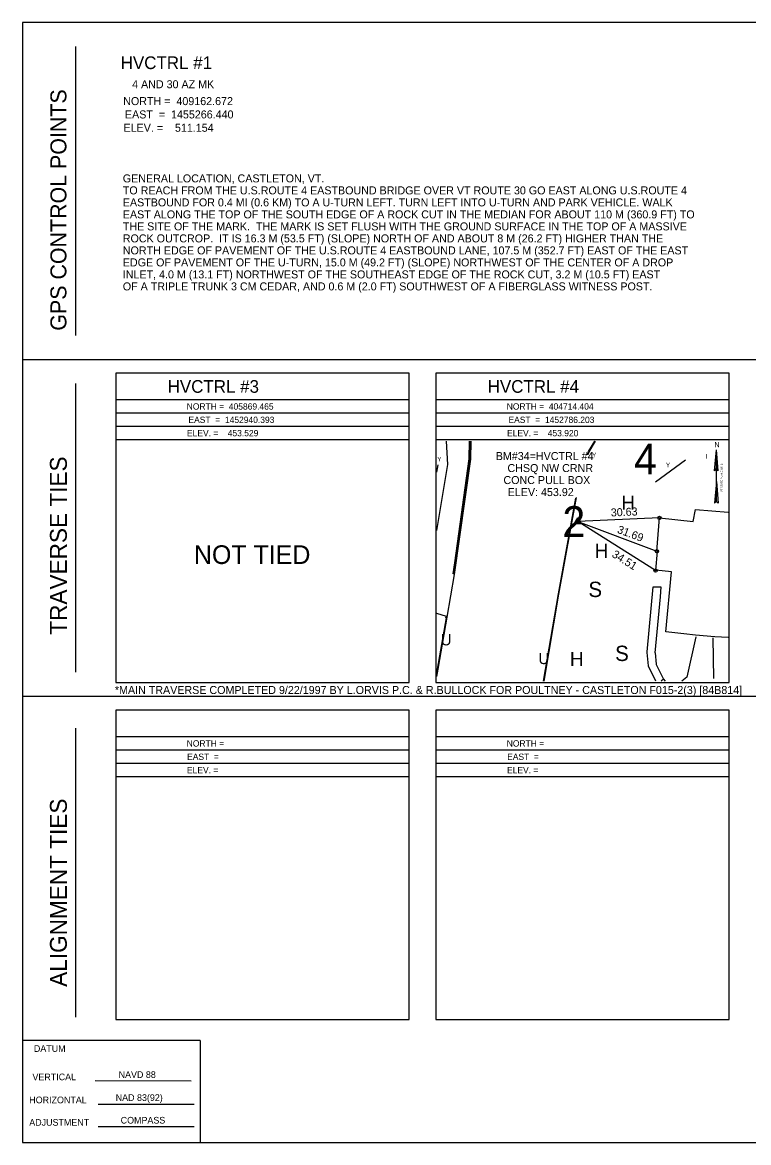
# Model space of a CAD drawing. Extents: x 1452748 to 1453388, y 402871 to 403291.
# Drawn here: x 1452747.7 to 1453020, y 402870.9 to 403290.9 of the extents above; entities that cross this region are included whole.
import ezdxf

# ---------------------------------------------------------------- set-up
doc = ezdxf.new("R2010")
doc.units = 0
for name, color, linetype in [('C_C', 7, 'Continuous'), ('CBP', 7, 'Continuous'), ('CPSM', 7, 'Continuous'), ('Default', 7, 'Continuous'), ('Level 1', 7, 'Continuous'), ('Level 11', 7, 'Continuous'), ('Level 12', 7, 'Continuous'), ('Level 13', 7, 'Continuous'), ('Level 14', 7, 'Continuous'), ('Level 15', 7, 'Continuous'), ('Level 16', 7, 'Continuous'), ('Level 43', 7, 'Continuous'), ('NBL1', 7, 'Continuous'), ('NBL2', 7, 'Continuous'), ('NNA_P', 7, 'Continuous')]:
    doc.layers.add(name, color=color, linetype=linetype)

msp = doc.modelspace()

# ---------------------------------------------------------------- linework, layer by layer
at = {"layer": 'CBP'}
for centre, radius in [((1452986.52, 403105.09), 0.625), ((1452986.52, 403105.09), 0.0833), ((1452985.59, 403092.61), 0.625), ((1452985.59, 403092.61), 0.0833), ((1452985.12, 403085.37), 0.625), ((1452985.12, 403085.37), 0.0833)]:
    msp.add_circle(centre, radius, dxfattribs=at)
at = {"layer": 'CPSM'}
for p, q in [((1452954.66, 403103.04), (1452955.91, 403105.2)), ((1452954.66, 403103.04), (1452955.92, 403103.76)), ((1452957.16, 403103.04), (1452955.91, 403105.2)), ((1452955.92, 403103.76), (1452955.91, 403105.2)), ((1452955.92, 403103.76), (1452955.92, 403103.76)), ((1452955.92, 403103.76), (1452957.16, 403103.04)), ((1452954.66, 403103.04), (1452957.16, 403103.04))]:
    msp.add_line(p, q, dxfattribs=at)
at = {"layer": 'Default'}
for p, q in [((1452986.52, 403105.09), (1452955.92, 403103.76)), ((1452955.92, 403103.76), (1452985.59, 403092.61)), ((1452985.12, 403085.37), (1452955.92, 403103.76))]:
    msp.add_line(p, q, dxfattribs=at)
at = {"layer": 'Level 11'}
for p, q in [((1452907.2, 403125.18), (1452906.75, 403133.85)), ((1452915.24, 403133.85), (1452915.08, 403127.24)), ((1452915.37, 403133.85), (1452915.23, 403127.2)), ((1452915.6, 403127.09), (1452915.8, 403133.85)), ((1452915.76, 403127.1), (1452916, 403133.85)), ((1452959.93, 403129.96), (1452962.34, 403133.85)), ((1452960.17, 403129.84), (1452962.59, 403133.85)), ((1452959.54, 403128.83), (1452959.93, 403129.96)), ((1452959.85, 403128.94), (1452960.17, 403129.84)), ((1452903.07, 403100.45), (1452907.2, 403125.18)), ((1452909.65, 403083.95), (1452915.76, 403127.1)), ((1452909.67, 403084.19), (1452915.6, 403127.09)), ((1452915.08, 403127.24), (1452909.75, 403088.26)), ((1452915.23, 403127.2), (1452909.81, 403088.14)), ((1452948.73, 403076.64), (1452955.23, 403112.5)), ((1452948.87, 403076.47), (1452955.48, 403112.75)), ((1452909.75, 403088.26), (1452909.06, 403084.16)), ((1452909.81, 403088.14), (1452909.22, 403084.21)), ((1452906.92, 403067.89), (1452909.65, 403083.95)), ((1452909.22, 403084.21), (1452909.67, 403084.19)), ((1452943.08, 403043.88), (1452948.73, 403076.64)), ((1452943.31, 403043.88), (1452948.87, 403076.47)), ((1452906.65, 403068.12), (1452903.07, 403069.31)), ((1452903.37, 403048.34), (1452906.74, 403067.64)), ((1452903.58, 403048.39), (1452906.92, 403067.89)), ((1452906.74, 403067.64), (1452906.29, 403067.78)), ((1453000.13, 403060.53), (1452996.85, 403045.45)), ((1453006.95, 403044.88), (1453006.63, 403060.13)), ((1452903.07, 403045.62), (1452903.58, 403048.39)), ((1452903.07, 403046.29), (1452903.37, 403048.34)), ((1452996.85, 403045.45), (1452994.92, 403043.88))]:
    msp.add_line(p, q, dxfattribs=at)
at = {"layer": 'Level 12'}
for p, q in [((1452903.07, 403122.29), (1452903.56, 403125.04)), ((1452981.96, 403054.9), (1452984.15, 403079.21)), ((1452984.15, 403079.21), (1452987.04, 403079.23)), ((1452987.04, 403079.23), (1452986.81, 403075.51)), ((1452986.81, 403075.51), (1452984.87, 403054.58)), ((1452981.98, 403054.71), (1452981.96, 403054.9)), ((1452982.42, 403049.68), (1452981.98, 403054.71)), ((1452984.87, 403054.58), (1452984.89, 403054.47)), ((1452984.89, 403054.47), (1452985.34, 403050.27)), ((1452982.43, 403049.52), (1452982.42, 403049.68)), ((1452985.24, 403043.88), (1452982.43, 403049.52)), ((1452985.34, 403050.27), (1452985.34, 403050.11)), ((1452985.34, 403050.11), (1452988, 403044.59)), ((1452988, 403044.59), (1452987.24, 403043.88)), ((1452988, 403044.59), (1452988.73, 403043.88))]:
    msp.add_line(p, q, dxfattribs=at)
at = {"layer": 'Level 13'}
for p, q in [((1452999.19, 403103.76), (1453000.07, 403108.29)), ((1453000.07, 403108.29), (1453012.27, 403107.24)), ((1452985.6, 403092.68), (1452986.53, 403105.08)), ((1452986.53, 403105.08), (1452999.19, 403103.76)), ((1452985.22, 403085.48), (1452985.84, 403092.54)), ((1452985.84, 403092.54), (1452985.6, 403092.68)), ((1452991.05, 403084.93), (1452985.22, 403085.48)), ((1452988.93, 403062.36), (1452991.05, 403084.93)), ((1452995.63, 403061.66), (1452988.93, 403062.36)), ((1453000, 403061.16), (1452995.63, 403061.66)), ((1453007.25, 403060.52), (1453000, 403061.16)), ((1453012.27, 403060.27), (1453007.25, 403060.52))]:
    msp.add_line(p, q, dxfattribs=at)
at = {"layer": 'Level 14'}
msp.add_line((1452985.1, 403118.66), (1452996.29, 403126.91), dxfattribs=at)
at = {"layer": 'NBL1'}
msp.add_lwpolyline([(1452747.67, 402870.89), (1453387.67, 402870.89), (1453387.67, 403290.89), (1452747.67, 403290.89)], close=True, dxfattribs=at)
at = {"layer": 'NBL2'}
for p, q in [((1452767.67, 403173.56), (1452767.67, 403281.89)), ((1452747.67, 403164.56), (1453387.67, 403164.56)), ((1452767.67, 403047.23), (1452767.67, 403155.56)), ((1452892.67, 403149.39), (1452782.67, 403149.39)), ((1453012.67, 403149.39), (1452902.67, 403149.39)), ((1452892.67, 403144.39), (1452782.67, 403144.39)), ((1453012.67, 403144.39), (1452902.67, 403144.39)), ((1452892.67, 403139.39), (1452782.67, 403139.39)), ((1453012.67, 403139.39), (1452902.67, 403139.39)), ((1452892.67, 403134.39), (1452782.67, 403134.39)), ((1453012.67, 403134.39), (1452902.67, 403134.39)), ((1452747.67, 403038.23), (1453387.67, 403038.23)), ((1452767.67, 402917.89), (1452767.67, 403026.23)), ((1452892.67, 403023.06), (1452782.67, 403023.06)), ((1453012.67, 403023.06), (1452902.67, 403023.06)), ((1452892.67, 403018.06), (1452782.67, 403018.06)), ((1453012.67, 403018.06), (1452902.67, 403018.06)), ((1452892.67, 403013.06), (1452782.67, 403013.06)), ((1453012.67, 403013.06), (1452902.67, 403013.06)), ((1452892.67, 403008.06), (1452782.67, 403008.06)), ((1453012.67, 403008.06), (1452902.67, 403008.06)), ((1452814.33, 402909.14), (1452747.67, 402909.14)), ((1452814.33, 402909.14), (1452814.33, 402870.89)), ((1452814.33, 402909.14), (1452814.33, 402870.89)), ((1452774.91, 402894.12), (1452810.91, 402894.09)), ((1452776.02, 402885.35), (1452812.02, 402885.35)), ((1452776.02, 402876.91), (1452812.02, 402876.88))]:
    msp.add_line(p, q, dxfattribs=at)
for points in [[(1452782.67, 403043.39), (1452892.67, 403043.39), (1452892.67, 403159.39), (1452782.67, 403159.39)], [(1452902.67, 403043.39), (1453012.67, 403043.39), (1453012.67, 403159.39), (1452902.67, 403159.39)], [(1452782.67, 402917.06), (1452892.67, 402917.06), (1452892.67, 403033.06), (1452782.67, 403033.06)], [(1452902.67, 402917.06), (1453012.67, 402917.06), (1453012.67, 403033.06), (1452902.67, 403033.06)]]:
    msp.add_lwpolyline(points, close=True, dxfattribs=at)
at = {"layer": 'NNA_P'}
for p, q in [((1453007.2, 403122.82), (1453007.89, 403130.61)), ((1453007.9, 403111.24), (1453007.89, 403130.61)), ((1453008.59, 403122.82), (1453007.89, 403130.61)), ((1453007.2, 403122.82), (1453007.89, 403123.59)), ((1453008.59, 403122.82), (1453007.9, 403123.59)), ((1453007.9, 403118.76), (1453007.18, 403110.6)), ((1453007.9, 403118.76), (1453008.62, 403110.6)), ((1453007.9, 403111.24), (1453007.18, 403110.6)), ((1453007.9, 403111.24), (1453008.62, 403110.6))]:
    msp.add_line(p, q, dxfattribs=at)

# ---------------------------------------------------------------- texts
at = {"layer": 'C_C'}
for s, p in [('BM#34=HVCTRL #4', (1452925.17, 403126.8)), ('CHSQ NW CRNR', (1452929.55, 403122.3)), ('CONC PULL BOX', (1452928.05, 403117.8)), ('ELEV: 453.92', (1452929.64, 403113.3))]:
    msp.add_text(s, height=3, dxfattribs=at).set_placement(p)
at = {"layer": 'Default'}
for s, height, p in [('GENERAL LOCATION, CASTLETON, VT.', 3, (1452785.32, 403230.91)), ('TO REACH FROM THE U.S.ROUTE 4 EASTBOUND BRIDGE OVER VT ROUTE 30 GO EAST ALONG U.S.ROUTE 4 ', 3, (1452785.32, 403226.41)), ('EASTBOUND FOR 0.4 MI (0.6 KM) TO A U-TURN LEFT. TURN LEFT INTO U-TURN AND PARK VEHICLE. WALK ', 3, (1452785.32, 403221.91)), ('EAST ALONG THE TOP OF THE SOUTH EDGE OF A ROCK CUT IN THE MEDIAN FOR ABOUT 110 M (360.9 FT) TO ', 3, (1452785.32, 403217.41)), ('THE SITE OF THE MARK.  THE MARK IS SET FLUSH WITH THE GROUND SURFACE IN THE TOP OF A MASSIVE ', 3, (1452785.32, 403212.91)), ('ROCK OUTCROP.  IT IS 16.3 M (53.5 FT) (SLOPE) NORTH OF AND ABOUT 8 M (26.2 FT) HIGHER THAN THE ', 3, (1452785.32, 403208.41)), ('NORTH EDGE OF PAVEMENT OF THE U.S.ROUTE 4 EASTBOUND LANE, 107.5 M (352.7 FT) EAST OF THE EAST ', 3, (1452785.32, 403203.91)), ('EDGE OF PAVEMENT OF THE U-TURN, 15.0 M (49.2 FT) (SLOPE) NORTHWEST OF THE CENTER OF A DROP ', 3, (1452785.32, 403199.41)), ('INLET, 4.0 M (13.1 FT) NORTHWEST OF THE SOUTHEAST EDGE OF THE ROCK CUT, 3.2 M (10.5 FT) EAST ', 3, (1452785.32, 403194.91)), ('OF A TRIPLE TRUNK 3 CM CEDAR, AND 0.6 M (2.0 FT) SOUTHWEST OF A FIBERGLASS WITNESS POST.', 3, (1452785.32, 403190.41)), ('NOT TIED', 7, (1452811.98, 403087.84)), ('*MAIN TRAVERSE COMPLETED 9/22/1997 BY L.ORVIS P.C. & R.BULLOCK FOR POULTNEY - CASTLETON F015-2(3) [84B814]', 3, (1452782.35, 403039.09))]:
    msp.add_text(s, height=height, dxfattribs=at).set_placement(p)
for s, rotation, p in [('30.63', 2.4846, (1452968.36, 403105.63)), ('31.69', 339.4125, (1452970.46, 403099.59)), ('34.51', 327.8079, (1452968.45, 403090.73))]:
    msp.add_text(s, height=3, rotation=rotation, dxfattribs=at).set_placement(p)
at = {"layer": 'Level 1'}
msp.add_text('2', height=11.5, dxfattribs=at).set_placement((1452950.16, 403098.01))
at = {"layer": 'Level 14'}
for s, height, p in [('H', 5.3, (1452972.24, 403108.14)), ('H', 5.3, (1452962.25, 403090.14)), ('S', 5.75, (1452959.9, 403075.44)), ('S', 5.75, (1452969.92, 403051.45)), ('H', 5.3, (1452952.95, 403049.58))]:
    msp.add_text(s, height=height, dxfattribs=at).set_placement(p)
at = {"layer": 'Level 15'}
for s, height, p in [('4', 11.5, (1452977.03, 403121.39)), ('I', 1.7, (1453003.83, 403127.32))]:
    msp.add_text(s, height=height, dxfattribs=at).set_placement(p)
at = {"layer": 'Level 16'}
for p in [(1452904.52, 403057.32), (1452941.13, 403050.3)]:
    msp.add_text('U', height=4.22, dxfattribs=at).set_placement(p)
at = {"layer": 'Level 43'}
for p in [(1452961.29, 403127.85), (1452903.24, 403126.29), (1452988.98, 403124.13)]:
    msp.add_text('Y', height=1.7, dxfattribs=at).set_placement(p)
at = {"layer": 'NBL2'}
for s, height, p in [('     HVCTRL #1     ', 4.75, (1452775.7, 403273.39)), ('   4 AND 30 AZ MK   ', 3, (1452785.47, 403266.2)), ('NORTH =  409162.672 ', 3, (1452785.47, 403259.89)), ('EAST  =  1455266.440', 3, (1452786.12, 403254.89)), ('ELEV. =    511.154  ', 3, (1452785.58, 403249.89)), ('     HVCTRL #3     ', 4.75, (1452793.31, 403152.02)), ('     HVCTRL #4     ', 4.75, (1452913.31, 403152.02)), ('NORTH =  405869.465 ', 2.375, (1452809.28, 403145.71)), ('NORTH =  404714.404 ', 2.375, (1452929.28, 403145.71)), ('EAST  =  1452940.393', 2.375, (1452809.93, 403140.71)), ('EAST  =  1452786.203', 2.375, (1452929.93, 403140.71)), ('ELEV. =    453.529  ', 2.375, (1452809.39, 403135.71)), ('ELEV. =    453.920  ', 2.375, (1452929.39, 403135.71)), ('NORTH =             ', 2.375, (1452809.28, 403019.37)), ('NORTH =             ', 2.375, (1452929.28, 403019.37)), ('EAST  =             ', 2.375, (1452809.43, 403014.37)), ('EAST  =             ', 2.375, (1452929.43, 403014.37)), ('ELEV. =             ', 2.375, (1452809.39, 403009.37)), ('ELEV. =             ', 2.375, (1452929.39, 403009.37)), ('DATUM', 2.5, (1452751.98, 402904.91)), ('  NAVD 88 ', 2.5, (1452781.89, 402895.13)), ('HORIZONTAL', 2.5, (1452750.24, 402885.64)), ('NAD 83(92) ', 2.5, (1452782.65, 402886.52)), ('ADJUSTMENT', 2.5, (1452750.24, 402877.21)), ('  COMPASS ', 2.5, (1452782.66, 402878.03))]:
    msp.add_text(s, height=height, dxfattribs=at).set_placement(p)
for s, height, rotation, p in [('GPS CONTROL POINTS', 6, 90, (1452764.17, 403175.31)), ('TRAVERSE TIES', 6.3332, 90, (1452764.33, 403061.33)), ('ALIGNMENT TIES', 6.3332, 90, (1452764.33, 402929.3)), ('VERTICAL', 2.5, 0.1439, (1452751.44, 402894.24))]:
    msp.add_text(s, height=height, rotation=rotation, dxfattribs=at).set_placement(p)
at = {"layer": 'NNA_P'}
msp.add_text('N', height=1.97, dxfattribs=at).set_placement((1453007.13, 403131.62))
msp.add_text('VT STATE PLANE GRID', height=0.7, rotation=90.0204, dxfattribs=at).set_placement((1453010.25, 403114.8))

doc.saveas('drawing.dxf')
